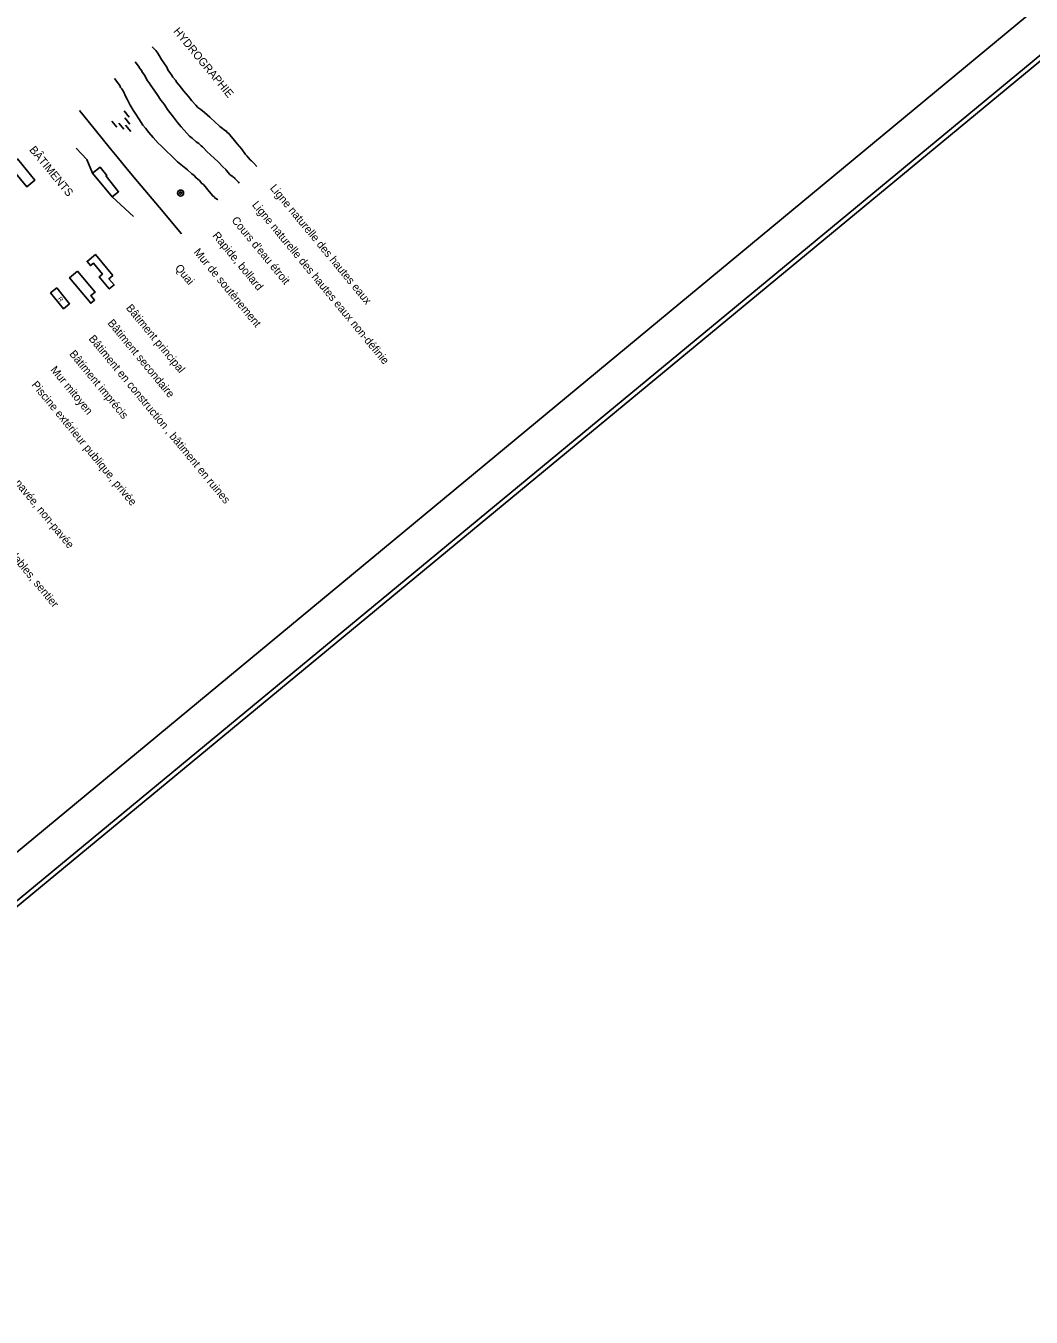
# Model space of a CAD drawing. Extents: x 347312 to 350503, y 6073086 to 6076432.
# Drawn here: x 349412 to 349915, y 6073086 to 6073732 of the extents above; entities that cross this region are included whole.
import ezdxf

# ---------------------------------------------------------------- set-up
doc = ezdxf.new("R2010")
doc.units = 0
for name, color, linetype in [('Level 10', 7, 'Continuous'), ('Level 31', 7, 'Continuous'), ('Level 4', 7, 'Continuous'), ('Level 6', 7, 'Continuous'), ('Level 60', 7, 'Continuous'), ('Level 63', 7, 'Continuous')]:
    doc.layers.add(name, color=color, linetype=linetype)

msp = doc.modelspace()

# ---------------------------------------------------------------- linework, layer by layer
at = {"layer": 'Level 10'}
msp.add_lwpolyline([(349445.82, 6073658.31), (349449.7, 6073661.27), (349452.92, 6073657.21), (349452.58, 6073656.91), (349458.84, 6073649.03), (349455.66, 6073646.49)], dxfattribs=at)
for radius in [1.5, 0.6]:
    msp.add_circle((349489.86, 6073648.4), radius, dxfattribs=at)
at = {"layer": 'Level 31'}
for points in [[(349408.36, 6073665.43), (349417.04, 6073654.91), (349412.98, 6073651.55), (349404.32, 6073662.07)], [(349455.96, 6073607.17), (349447.3, 6073617.65), (349443.1, 6073614.21), (349444.8, 6073612.13), (349446.28, 6073613.35), (349450.78, 6073607.85), (349449.2, 6073606.55), (349454.18, 6073600.47), (349456.58, 6073602.45), (349454, 6073605.57)], [(349438.36, 6073609.37), (349447.08, 6073598.83), (349444.96, 6073597.11), (349446.82, 6073594.87), (349444.9, 6073593.29), (349434.34, 6073606.03)], [(349427.92, 6073600.95), (349434.38, 6073593.05), (349431.34, 6073590.55), (349424.86, 6073598.49)]]:
    msp.add_lwpolyline(points, close=True, dxfattribs=at)
at = {"layer": 'Level 4'}
for points in [[(349475.66, 6073721.55), (349477.54, 6073719.61), (349478.5, 6073718.39), (349479.22, 6073717.21), (349480.34, 6073715.23), (349481.42, 6073713.55), (349482.98, 6073711.39), (349483.24, 6073710.43), (349483.54, 6073710.05), (349484.8, 6073708.23), (349485.36, 6073707.55), (349486.04, 6073706.37), (349487.32, 6073704.81), (349487.98, 6073703.67), (349489.16, 6073702.29), (349491.56, 6073699.35), (349493.84, 6073696.61), (349495.54, 6073694.53), (349497.4, 6073692.27), (349498.56, 6073691.21), (349500, 6073690.11), (349501.76, 6073688.67), (349504.52, 6073686.33), (349507.24, 6073683.63), (349508.8, 6073682.35), (349509.44, 6073681.65), (349510.16, 6073681.15), (349512.32, 6073679.47), (349512.64, 6073679.45), (349513.18, 6073678.75), (349513.94, 6073678.19), (349514.38, 6073677.67), (349516.2, 6073675.45), (349518.22, 6073673.05), (349520.5, 6073670.29), (349522.32, 6073667.75), (349522.9, 6073667.07), (349524.6, 6073665.01), (349525.04, 6073664.75), (349525.34, 6073664.43), (349526.06, 6073663.87), (349526.5, 6073663.39), (349527.92, 6073661.63)], [(349467.16, 6073713.97), (349468.88, 6073711.89), (349469.56, 6073710.73), (349470.56, 6073709.51), (349470.5, 6073709.19), (349471.82, 6073707.37), (349473.28, 6073704.57), (349474.14, 6073703.55), (349474.94, 6073702.21), (349476.64, 6073699.81), (349478.2, 6073697.65), (349480.02, 6073694.81), (349481.58, 6073692.89), (349483.24, 6073690.23), (349484.5, 6073688.67), (349486.24, 6073686.29), (349488.32, 6073683.71), (349490.2, 6073681.47), (349493.06, 6073678.31), (349494.32, 6073676.81), (349495.64, 6073675.87), (349497.68, 6073674.05), (349499.02, 6073673.11), (349500.1, 6073672.03), (349500.86, 6073671.51), (349501.46, 6073670.79), (349502.88, 6073669.37), (349504.92, 6073667.29), (349506.66, 6073665.85), (349508.68, 6073664.03), (349510.96, 6073661.57), (349512.42, 6073660.19), (349512.68, 6073659.85), (349514.52, 6073657.61), (349515.3, 6073657.07), (349515.6, 6073657.01), (349515.86, 6073656.69), (349516.74, 6073655.95), (349517, 6073655.65), (349518.46, 6073654.17), (349518.74, 6073653.83), (349519.14, 6073653.33)], [(349456.88, 6073705.65), (349459.56, 6073702.11), (349459.82, 6073701.13), (349460.4, 6073700.45), (349461.52, 6073698.79), (349462.28, 6073696.83), (349463.24, 6073694.97), (349464.6, 6073692.39), (349466.14, 6073689.91), (349467.54, 6073687.85), (349468.9, 6073685.53), (349471.04, 6073682.33), (349472.28, 6073680.77), (349473.98, 6073678.73), (349476.14, 6073676.15), (349478.68, 6073673.33), (349480.16, 6073671.93), (349483.06, 6073669.11), (349485.2, 6073667.15), (349488.36, 6073663.95), (349489.96, 6073662.71), (349493.32, 6073659.95), (349495.48, 6073657.97), (349496.64, 6073657.23), (349497.62, 6073655.99), (349499.24, 6073654.73), (349500.52, 6073653.21), (349501.1, 6073652.81), (349501.42, 6073652.45), (349504.08, 6073649.17), (349505.92, 6073646.97), (349506.64, 6073646.43), (349507.14, 6073645.89), (349507.54, 6073645.69), (349508.3, 6073645.15), (349508.44, 6073644.95)], [(349439.38, 6073689.61), (349447.08, 6073680.07), (349454.78, 6073670.55), (349458.1, 6073666.45), (349463.18, 6073660.31), (349468.3, 6073654.23), (349479.34, 6073641.09), (349490.36, 6073627.93)], [(349437.7, 6073670.85), (349442.96, 6073665.23), (349445.82, 6073658.31), (349455.66, 6073646.49), (349466.38, 6073636.71)]]:
    msp.add_lwpolyline(points, dxfattribs=at)
at = {"layer": 'Level 6'}
for p, q in [((349461.64, 6073689.51), (349464.18, 6073686.41)), ((349462, 6073685.93), (349464.54, 6073682.85)), ((349455.48, 6073684.39), (349458.02, 6073681.33)), ((349458.92, 6073683.35), (349461.48, 6073680.29)), ((349462.38, 6073682.35), (349464.9, 6073679.25))]:
    msp.add_line(p, q, dxfattribs=at)
at = {"layer": 'Level 60'}
for points in [[(349159.76, 6073089.49), (347315.28, 6075321.63), (348655.04, 6076428.72), (350499.52, 6074196.58)], [(350097.64, 6074648.45), (350470.23, 6074198.33), (349166.42, 6073119.09), (348793.83, 6073569.21)]]:
    msp.add_lwpolyline(points, close=True, dxfattribs=at)
msp.add_lwpolyline([(350502.67, 6074196.28), (349159.46, 6073086.35)], dxfattribs=at)

# ---------------------------------------------------------------- texts
at = {"layer": 'Level 31'}
msp.add_text('R', height=2.25, rotation=309.10455, dxfattribs=at).set_placement((349428.24, 6073595.45))
at = {"layer": 'Level 60'}
for s, p in [('HYDROGRAPHIE', (349486.02, 6073729.15)), ('BÂTIMENTS', (349413.98, 6073669.87))]:
    msp.add_text(s, height=4, rotation=309.57347, dxfattribs=at).set_placement(p)
at = {"layer": 'Level 63'}
for s, p in [('Ligne naturelle des hautes eaux', (349534.32, 6073650.77)), ('Ligne naturelle des hautes eaux non-définie', (349525.36, 6073642.37)), ("Cours d'eau étroit", (349515.1, 6073634.67)), ('Rapide, bollard', (349505.56, 6073627.01)), ('Mur de soutènement', (349496.2, 6073618.75)), ('Quai', (349486.8, 6073610.81)), ('Bâtiment principal', (349462.32, 6073590.81)), ('Bâtiment secondaire', (349453.1, 6073583.27)), ('Bâtiment en construction , bâtiment en ruines', (349443.66, 6073575.43)), ('Bâtiment imprécis', (349433.96, 6073567.81)), ('Mur mitoyen', (349424.56, 6073559.89)), ('Piscine extérieur publique, privée', (349415.06, 6073552.39)), ('Route ou rue pavée, non-pavée', (349386, 6073528.25)), ('Voies piétonnières et cyclables, sentier', (349367.38, 6073511.99))]:
    msp.add_text(s, height=4, rotation=309.57347, dxfattribs=at).set_placement(p)

doc.saveas('drawing.dxf')
